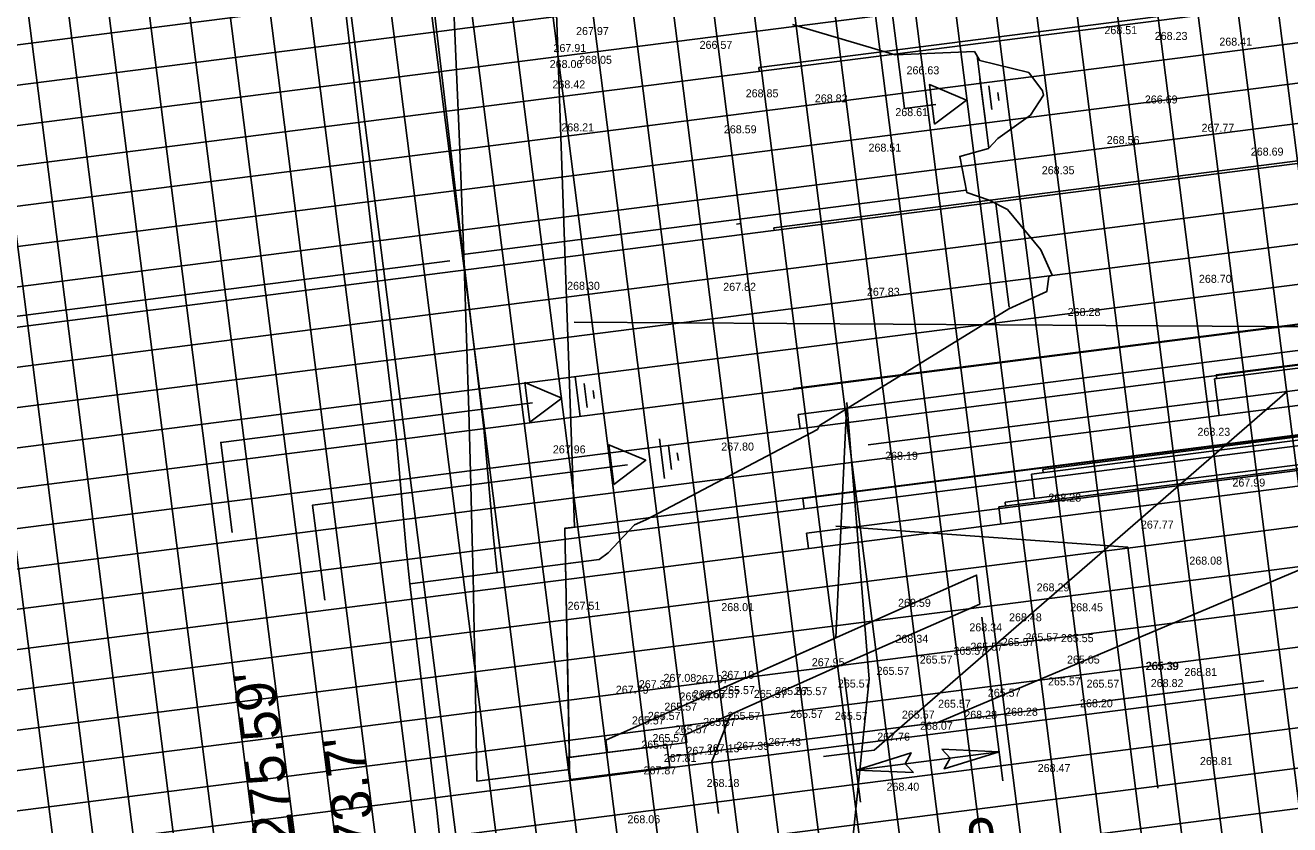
# Model space of a CAD drawing. Extents: x 2166991 to 2168450, y 842134 to 844444.
# Drawn here: x 2167712.5 to 2167870.5, y 843313.8 to 843413.8 of the extents above; entities that cross this region are included whole.
import ezdxf

# ---------------------------------------------------------------- set-up
doc = ezdxf.new("R2010")
doc.units = 0
for name, color, linetype in [('Exist Hydrographic Top of Bank', 7, 'Continuous'), ('Exist Plan Preparation Drainage Notes Label', 7, 'Continuous'), ('Old_Level_18', 7, 'Continuous'), ('Prop Boundary Buffer Zone 1', 7, 'Continuous'), ('Prop Boundary Buffer Zone 2', 7, 'Continuous'), ('Prop Drainage Structure Bridge', 7, 'Continuous'), ('Prop Drainage Structure Drop Inlet Grate 2 Narrow Slots and Flat Grates 840 29 CELL', 7, 'Continuous'), ('Prop Drainage Structure Drop Inlet Grate 2 Wide Slots and Flat Grates 840 20 TB Label', 7, 'Continuous'), ('Prop Drainage Structure Pipe Collar Label', 7, 'Continuous'), ('Prop Drainage Structure Pipe CSP 18in Label', 7, 'Continuous'), ('Prop Drainage Structure Scour Hole CELL', 7, 'Continuous'), ('Prop Drainage Structure Scour Hole Label', 7, 'Continuous'), ('Prop Erosion Rip Rap Class II', 7, 'Continuous'), ('Prop Erosion Rip Rap Class II Label', 7, 'Continuous'), ('Prop Plan Preparation Excavation Hatching Label', 7, 'Continuous'), ('Scratch_Level_3', 7, 'Continuous')]:
    doc.layers.add(name, color=color, linetype=linetype)

msp = doc.modelspace()

# ---------------------------------------------------------------- linework, layer by layer
at = {"layer": 'Exist Hydrographic Top of Bank'}
for p, q in [((2167801.93, 843388.97), (2167801.38, 843388.9)), ((2167765.56, 843384.32), (2167668.02, 843371.86)), ((2167832.06, 843339.76), (2167834.67, 843319.3)), ((2167814.9, 843332.2), (2167816.89, 843316.6)), ((2167816.37, 843320.64), (2167834.21, 843322.92))]:
    msp.add_line(p, q, dxfattribs=at)
for points in [[(2167895.15, 843315.83), (2167893.14, 843331.53), (2167887.44, 843375.99), (2167781.12, 843376.66)], [(2167854.04, 843318.38), (2167850.29, 843348.53), (2167813.82, 843351.12)], [(2167799.13, 843315.18), (2167798.3, 843321.71), (2167800.64, 843327.58)]]:
    msp.add_lwpolyline(points, dxfattribs=at)
for points in [[(2167827.08, 843323.23), (2167834.21, 843322.92), (2167827.35, 843320.79), (2167828.09, 843322.14)], [(2167823.5, 843320.33), (2167816.37, 843320.64), (2167823.23, 843322.78), (2167822.49, 843321.42)]]:
    msp.add_lwpolyline(points, close=True, dxfattribs=at)
at = {"layer": 'Exist Plan Preparation Drainage Notes Label'}
for p, q in [((2167933.95, 842789.5), (2167775.57, 844029.42)), ((2167884.35, 842783.16), (2167725.98, 844023.09)), ((2167834.76, 842776.83), (2167676.38, 844016.75)), ((2167785.16, 842770.49), (2167626.78, 844010.42)), ((2167940.7, 842815.56), (2167788.66, 844005.89)), ((2167945.66, 842816.2), (2167793.62, 844006.52)), ((2167925.82, 842813.66), (2167773.78, 844003.99)), ((2167935.74, 842814.93), (2167783.7, 844005.26)), ((2167915.9, 842812.39), (2167763.86, 844002.72)), ((2167920.86, 842813.03), (2167768.82, 844003.36)), ((2167901.03, 842810.49), (2167748.98, 844000.82)), ((2167905.98, 842811.13), (2167753.94, 844001.46)), ((2167910.94, 842811.76), (2167758.9, 844002.09)), ((2167891.11, 842809.23), (2167739.06, 843999.56)), ((2167896.07, 842809.86), (2167744.02, 844000.19)), ((2167876.23, 842807.33), (2167724.19, 843997.66)), ((2167886.15, 842808.59), (2167734.11, 843998.92)), ((2167866.31, 842806.06), (2167714.27, 843996.39)), ((2167871.27, 842806.69), (2167719.23, 843997.02)), ((2167851.43, 842804.16), (2167699.39, 843994.49)), ((2167856.39, 842804.79), (2167704.35, 843995.12)), ((2167861.35, 842805.43), (2167709.31, 843995.76)), ((2167841.51, 842802.89), (2167689.47, 843993.22)), ((2167846.47, 842803.53), (2167694.43, 843993.85)), ((2167826.63, 842800.99), (2167674.59, 843991.32)), ((2167836.55, 842802.26), (2167684.51, 843992.59)), ((2167816.71, 842799.72), (2167664.67, 843990.05)), ((2167821.67, 842800.36), (2167669.63, 843990.69)), ((2167801.83, 842797.82), (2167649.79, 843988.15)), ((2167806.79, 842798.46), (2167654.75, 843988.79)), ((2167811.75, 842799.09), (2167659.71, 843989.42)), ((2167791.91, 842796.56), (2167639.87, 843986.89)), ((2167796.87, 842797.19), (2167644.83, 843987.52)), ((2167786.95, 842795.92), (2167634.91, 843986.25)), ((2168149.81, 843467.31), (2167653.84, 843403.96)), ((2168150.44, 843462.35), (2167654.47, 843399)), ((2168151.08, 843457.39), (2167655.11, 843394.04)), ((2168151.71, 843452.43), (2167655.74, 843389.08)), ((2168152.35, 843447.47), (2167631.58, 843380.95)), ((2168152.98, 843442.51), (2167657.01, 843379.16)), ((2168153.61, 843437.55), (2167657.64, 843374.2)), ((2168154.25, 843432.59), (2167658.28, 843369.24)), ((2168154.88, 843427.63), (2167658.91, 843364.28)), ((2168155.51, 843422.67), (2167659.54, 843359.32)), ((2168156.15, 843417.71), (2167660.18, 843354.36)), ((2168156.78, 843412.75), (2167660.81, 843349.4)), ((2168157.41, 843407.79), (2167661.44, 843344.44)), ((2168158.05, 843402.83), (2167662.08, 843339.48)), ((2168158.68, 843397.87), (2167637.91, 843331.35)), ((2168159.31, 843392.91), (2167663.34, 843329.56)), ((2168159.95, 843387.95), (2167663.98, 843324.6)), ((2168160.58, 843382.99), (2167664.61, 843319.64)), ((2168161.21, 843378.03), (2167665.24, 843314.68)), ((2168161.85, 843373.07), (2167665.88, 843309.72)), ((2168162.48, 843368.11), (2167666.51, 843304.76)), ((2168163.11, 843363.15), (2167667.14, 843299.8)), ((2168163.75, 843358.2), (2167667.78, 843294.84)), ((2168164.38, 843353.24), (2167668.41, 843289.89))]:
    msp.add_line(p, q, dxfattribs=at)
at = {"layer": 'Old_Level_18'}
for p, q in [((2167832.93, 843398.43), (2167831.46, 843409.95)), ((2167835.48, 843378.51), (2167833.82, 843391.48))]:
    msp.add_line(p, q, dxfattribs=at)
at = {"layer": 'Prop Boundary Buffer Zone 1'}
for p, q in [((2168087.87, 843444.75), (2167804.17, 843408.52)), ((2168086.81, 843424.32), (2167806.08, 843388.46)), ((2167804.23, 843408.05), (2167804.17, 843408.52)), ((2168086.26, 843403.82), (2167808.5, 843368.34)), ((2168086.42, 843400.54), (2167809.11, 843365.12)), ((2168085.19, 843389.79), (2167809.7, 843354.6)), ((2167806.12, 843388.13), (2167806.08, 843388.46)), ((2168085.19, 843385.4), (2167810.15, 843350.27)), ((2167808.51, 843368.27), (2167808.5, 843368.34)), ((2167809.34, 843363.33), (2167809.11, 843365.12)), ((2167809.86, 843353.32), (2167809.7, 843354.6)), ((2167810.4, 843348.35), (2167810.15, 843350.27))]:
    msp.add_line(p, q, dxfattribs=at)
at = {"layer": 'Prop Boundary Buffer Zone 2'}
for p, q in [((2167767.21, 843385.11), (2167830.11, 843393.15)), ((2167760.56, 843343.94), (2167784.24, 843346.96))]:
    msp.add_line(p, q, dxfattribs=at)
for points in [[(2167771.47, 843345.33), (2167771.01, 843349.66), (2167769.81, 843363.4), (2167767.4, 843383.52), (2167762.64, 843423.88), (2167758.03, 843464.59)], [(2167760.56, 843343.94), (2167760.1, 843348.27), (2167758.9, 843362.01), (2167756.48, 843382.13), (2167751.73, 843422.48), (2167747.12, 843463.2)]]:
    msp.add_lwpolyline(points, dxfattribs=at)
at = {"layer": 'Prop Drainage Structure Bridge'}
msp.add_lwpolyline([(2167784.24, 843346.96), (2167785.37, 843347.8), (2167788.65, 843351.29), (2167790.08, 843351.91), (2167811.52, 843363.23), (2167811.76, 843363.73), (2167835.45, 843378.32), (2167840.17, 843380.47), (2167840.43, 843382.37), (2167840.86, 843382.52), (2167839.45, 843385.69), (2167835.28, 843390.74), (2167832.96, 843391.91), (2167830.17, 843392.87), (2167829.29, 843397.37), (2167832.89, 843398.38), (2167834.04, 843399.62), (2167838.15, 843402.55), (2167839.75, 843405.06), (2167839.63, 843405.57), (2167837.93, 843407.87), (2167831.79, 843409.39), (2167831.14, 843410.52), (2167821.21, 843410.07), (2167808.38, 843413.88)], dxfattribs=at)
at = {"layer": 'Prop Drainage Structure Drop Inlet Grate 2 Narrow Slots and Flat Grates 840 29 CELL'}
msp.add_lwpolyline([(2167757.79, 842963.56), (2167770.55, 842995.45), (2167773.98, 843046.3), (2167776.61, 843068.3), (2167777.35, 843097.13), (2167787.62, 843148.85), (2167792.18, 843199.84), (2167793.61, 843214.01), (2167797.76, 843250.96), (2167815.06, 843303.58), (2167817.99, 843332.01), (2167815.17, 843366.59)], dxfattribs=at)
at = {"layer": 'Prop Drainage Structure Drop Inlet Grate 2 Wide Slots and Flat Grates 840 20 TB Label'}
msp.add_lwpolyline([(2167785.27, 843322.82), (2167785.06, 843324.39), (2167831.4, 843345.02), (2167831.8, 843341.39), (2167814.14, 843333.63), (2167795.08, 843325.09), (2167795.19, 843324.06), (2167792.71, 843323.75)], close=True, dxfattribs=at)
at = {"layer": 'Prop Drainage Structure Pipe Collar Label'}
for p, q in [((2167814.98, 843365.72), (2167814.45, 843369.88)), ((2167929.12, 843369.93), (2167826.58, 843326.57))]:
    msp.add_line(p, q, dxfattribs=at)
at = {"layer": 'Prop Drainage Structure Pipe CSP 18in Label'}
for p, q in [((2167779.93, 843350.85), (2167929.19, 843369.92)), ((2167821.41, 843325.93), (2167864.73, 843331.46)), ((2167848.71, 843329.41), (2167867.3, 843331.79)), ((2167792.9, 843322.27), (2167834.07, 843327.53)), ((2167780.32, 843322.19), (2167792.72, 843323.77)), ((2167793.05, 843321.04), (2167792.71, 843323.76)), ((2167768.96, 843319.23), (2167780.51, 843320.7)), ((2167770.59, 843319.44), (2167780.51, 843320.7)), ((2167780.67, 843319.46), (2167793.07, 843321.05))]:
    msp.add_line(p, q, dxfattribs=at)
for points in [[(2167780.51, 843320.7), (2167779.93, 843350.87), (2167781.17, 843351.03), (2167778.7, 843421.28), (2167777.46, 843421.13), (2167775.94, 843451.17)], [(2167768.96, 843319.23), (2167768.73, 843332.94), (2167768.63, 843337.97), (2167768.48, 843344.95), (2167768.38, 843349.4), (2167768.21, 843356.31), (2167767.95, 843365.56), (2167767.37, 843383.75), (2167767.32, 843385.13), (2167766.83, 843398.23), (2167765.91, 843419.65), (2167765.64, 843425.24), (2167764.98, 843438.32), (2167764.72, 843443.32), (2167764.37, 843449.7)]]:
    msp.add_lwpolyline(points, dxfattribs=at)
at = {"layer": 'Prop Drainage Structure Scour Hole CELL'}
msp.add_line((2167780.32, 843322.17), (2167780.67, 843319.45), dxfattribs=at)
msp.add_lwpolyline([(2167780.51, 843322.21), (2167780.02, 843346.42), (2167784.24, 843346.96), (2167785.37, 843347.8), (2167788.65, 843351.29), (2167790.08, 843351.91), (2167811.52, 843363.23), (2167811.76, 843363.73), (2167815.13, 843365.81), (2167813.8, 843337.17), (2167785.06, 843324.39), (2167785.27, 843322.82), (2167781.42, 843322.33)], close=True, dxfattribs=at)
at = {"layer": 'Prop Drainage Structure Scour Hole Label'}
for p, q in [((2168083.92, 843398.03), (2167861.12, 843369.57)), ((2168083.92, 843398.49), (2167861.36, 843370.07)), ((2168083.55, 843389.39), (2167839.68, 843358.24)), ((2168082.84, 843388.87), (2167838.25, 843357.63)), ((2168083.95, 843385.46), (2167834.18, 843353.55)), ((2168082.98, 843385.82), (2167834.96, 843354.14)), ((2167861.7, 843364.98), (2167861.12, 843369.57)), ((2167861.42, 843369.6), (2167861.36, 843370.07)), ((2167838.63, 843354.61), (2167838.25, 843357.63)), ((2167839.73, 843357.82), (2167839.68, 843358.24)), ((2167834.45, 843351.42), (2167834.18, 843353.55)), ((2167835.02, 843353.66), (2167834.96, 843354.14))]:
    msp.add_line(p, q, dxfattribs=at)
at = {"layer": 'Prop Erosion Rip Rap Class II'}
for points in [[(2167814.63, 843463.88), (2167822.41, 843403.37), (2167826.31, 843403.86)], [(2167775.92, 843366.58), (2167736.94, 843361.6), (2167738.37, 843350.34)], [(2167787.78, 843358.8), (2167748.42, 843353.78), (2167749.94, 843341.89)]]:
    msp.add_lwpolyline(points, dxfattribs=at)
at = {"layer": 'Prop Erosion Rip Rap Class II Label'}
for p, q in [((2167832.46, 843402.13), (2167831.83, 843407.09)), ((2167833.33, 843403.25), (2167832.95, 843406.22)), ((2167834.19, 843404.36), (2167834.07, 843405.36)), ((2167781.88, 843364.87), (2167781.25, 843369.83)), ((2167782.75, 843365.98), (2167782.37, 843368.96)), ((2167783.61, 843367.1), (2167783.49, 843368.1)), ((2167792.4, 843357.09), (2167791.76, 843362.05)), ((2167793.26, 843358.21), (2167792.88, 843361.18)), ((2167794.13, 843359.33), (2167794, 843360.32))]:
    msp.add_line(p, q, dxfattribs=at)
for points in [[(2167826.14, 843401.4), (2167825.51, 843406.36), (2167830.13, 843404.43)], [(2167775.56, 843364.13), (2167774.93, 843369.09), (2167779.55, 843367.16)], [(2167786.07, 843356.36), (2167785.44, 843361.32), (2167790.06, 843359.39)]]:
    msp.add_lwpolyline(points, close=True, dxfattribs=at)
at = {"layer": 'Prop Plan Preparation Excavation Hatching Label'}
msp.add_lwpolyline([(2167751.39, 842824.91), (2167752.39, 842844.74), (2167753.95, 842874.72), (2167755.15, 842897.27), (2167757.06, 842927.31), (2167757.92, 842945.41), (2167760.09, 842975.47), (2167761.25, 842993.97), (2167762.76, 843023.98), (2167763.76, 843044.55), (2167765.23, 843074.51), (2167766.29, 843095.78), (2167768.15, 843125.8), (2167769.02, 843139.96), (2167770.48, 843169.95), (2167771.39, 843188.46), (2167770.67, 843218.15), (2167770.25, 843236.07), (2167768.33, 843265.68), (2167767.02, 843285.86), (2167763.97, 843315.19), (2167760.56, 843343.94)], dxfattribs=at)
at = {"layer": 'Scratch_Level_3'}
for p, q in [((2167817.84, 843361.31), (2168278.64, 843420.17)), ((2167870.26, 843368), (2167818.59, 843323.14)), ((2167818.59, 843323.14), (2167812.28, 843322.33))]:
    msp.add_line(p, q, dxfattribs=at)

# ---------------------------------------------------------------- texts
at = {"layer": 'Exist Hydrographic Top of Bank'}
msp.add_text('TYP', height=5, rotation=97.279, dxfattribs=at).set_placement((2167836.81, 843302.55))
at = {"layer": 'Prop Erosion Rip Rap Class II'}
for s, p in [("100 YR WSEL  = 275.59'", (2167752.81, 843259.57)), ("25 YR WSEL  = 273.7'", (2167763.11, 843258.81))]:
    msp.add_text(s, height=5, rotation=97.279, dxfattribs=at).set_placement(p)
at = {"layer": 'Scratch_Level_3'}
for s, p in [('267.97', (2167781.35, 843412.56)), ('268.51', (2167847.38, 843412.67)), ('268.23', (2167853.67, 843411.95)), ('267.91', (2167778.53, 843410.44)), ('266.57', (2167796.79, 843410.83)), ('268.41', (2167861.74, 843411.23)), ('268.05', (2167781.74, 843408.96)), ('268.06', (2167778.05, 843408.43)), ('266.63', (2167822.65, 843407.65)), ('268.42', (2167778.4, 843405.89)), ('268.85', (2167802.55, 843404.77)), ('268.82', (2167811.19, 843404.14)), ('268.61', (2167821.25, 843402.42)), ('266.69', (2167852.43, 843404)), ('268.21', (2167779.51, 843400.51)), ('268.59', (2167799.82, 843400.27)), ('267.77', (2167859.52, 843400.46)), ('268.51', (2167817.9, 843397.98)), ('268.56', (2167847.67, 843398.93)), ('268.69', (2167865.67, 843397.48)), ('268.35', (2167839.55, 843395.15)), ('268.30', (2167780.23, 843380.7)), ('267.82', (2167799.74, 843380.57)), ('268.70', (2167859.19, 843381.57)), ('267.83', (2167817.7, 843379.95)), ('268.28', (2167842.79, 843377.42)), ('268.23', (2167859.01, 843362.44)), ('267.96', (2167778.45, 843360.24)), ('267.80', (2167799.49, 843360.59)), ('268.19', (2167819.97, 843359.44)), ('267.99', (2167863.38, 843356.09)), ('268.28', (2167840.38, 843354.21)), ('267.77', (2167851.94, 843350.83)), ('268.08', (2167857.99, 843346.33)), ('268.29', (2167838.91, 843342.98)), ('268.59', (2167821.59, 843341.05)), ('267.51', (2167780.29, 843340.68)), ('268.01', (2167799.5, 843340.51)), ('268.48', (2167835.46, 843339.24)), ('268.45', (2167843.11, 843340.49)), ('268.34', (2167830.5, 843337.98)), ('268.34', (2167821.27, 843336.55)), ('265.57', (2167834.56, 843336.14)), ('265.57', (2167837.52, 843336.74)), ('265.55', (2167841.94, 843336.63)), ('265.57', (2167828.51, 843335.05)), ('265.57', (2167830.63, 843335.56)), ('267.95', (2167810.81, 843333.62)), ('265.57', (2167824.3, 843333.95)), ('265.05', (2167842.7, 843333.95)), ('265.39', (2167852.51, 843333.14)), ('265.39', (2167852.6, 843333.17)), ('267.08', (2167792.28, 843331.66)), ('267.07', (2167796.33, 843331.5)), ('267.10', (2167799.51, 843332.04)), ('265.57', (2167818.91, 843332.54)), ('268.81', (2167857.37, 843332.4)), ('267.79', (2167786.32, 843330.18)), ('267.34', (2167789.19, 843330.87)), ('265.57', (2167799.61, 843330.13)), ('265.57', (2167806.24, 843330.02)), ('265.57', (2167808.65, 843330)), ('265.57', (2167814.07, 843330.95)), ('265.57', (2167832.81, 843329.8)), ('265.57', (2167840.33, 843331.22)), ('265.57', (2167845.15, 843330.94)), ('268.82', (2167853.17, 843331.01)), ('265.57', (2167794.28, 843329.34)), ('265.57', (2167795.95, 843329.62)), ('265.57', (2167797.71, 843329.63)), ('265.57', (2167803.57, 843329.66)), ('265.57', (2167826.59, 843328.43)), ('268.20', (2167844.33, 843328.49)), ('265.57', (2167790.32, 843326.91)), ('265.57', (2167792.38, 843328.06)), ('265.57', (2167800.29, 843326.91)), ('265.57', (2167808.11, 843327.16)), ('265.57', (2167813.7, 843326.91)), ('265.57', (2167822.07, 843327.07)), ('268.28', (2167829.87, 843327.05)), ('268.28', (2167834.97, 843327.42)), ('265.57', (2167788.33, 843326.34)), ('265.57', (2167793.69, 843325.22)), ('265.57', (2167797.24, 843326.15)), ('268.07', (2167824.34, 843325.67)), ('265.57', (2167790.9, 843324.13)), ('267.43', (2167805.37, 843323.65)), ('267.76', (2167818.99, 843324.31)), ('265.57', (2167789.51, 843323.32)), ('267.15', (2167795.15, 843322.54)), ('267.15', (2167797.68, 843322.86)), ('267.39', (2167801.39, 843323.16)), ('267.81', (2167792.31, 843321.64)), ('268.47', (2167839.04, 843320.39)), ('268.81', (2167859.32, 843321.26)), ('267.87', (2167789.78, 843320.09)), ('268.18', (2167797.67, 843318.52)), ('268.40', (2167820.15, 843318.05)), ('268.06', (2167787.77, 843313.98))]:
    msp.add_text(s, height=1, dxfattribs=at).set_placement(p)

doc.saveas('drawing.dxf')
